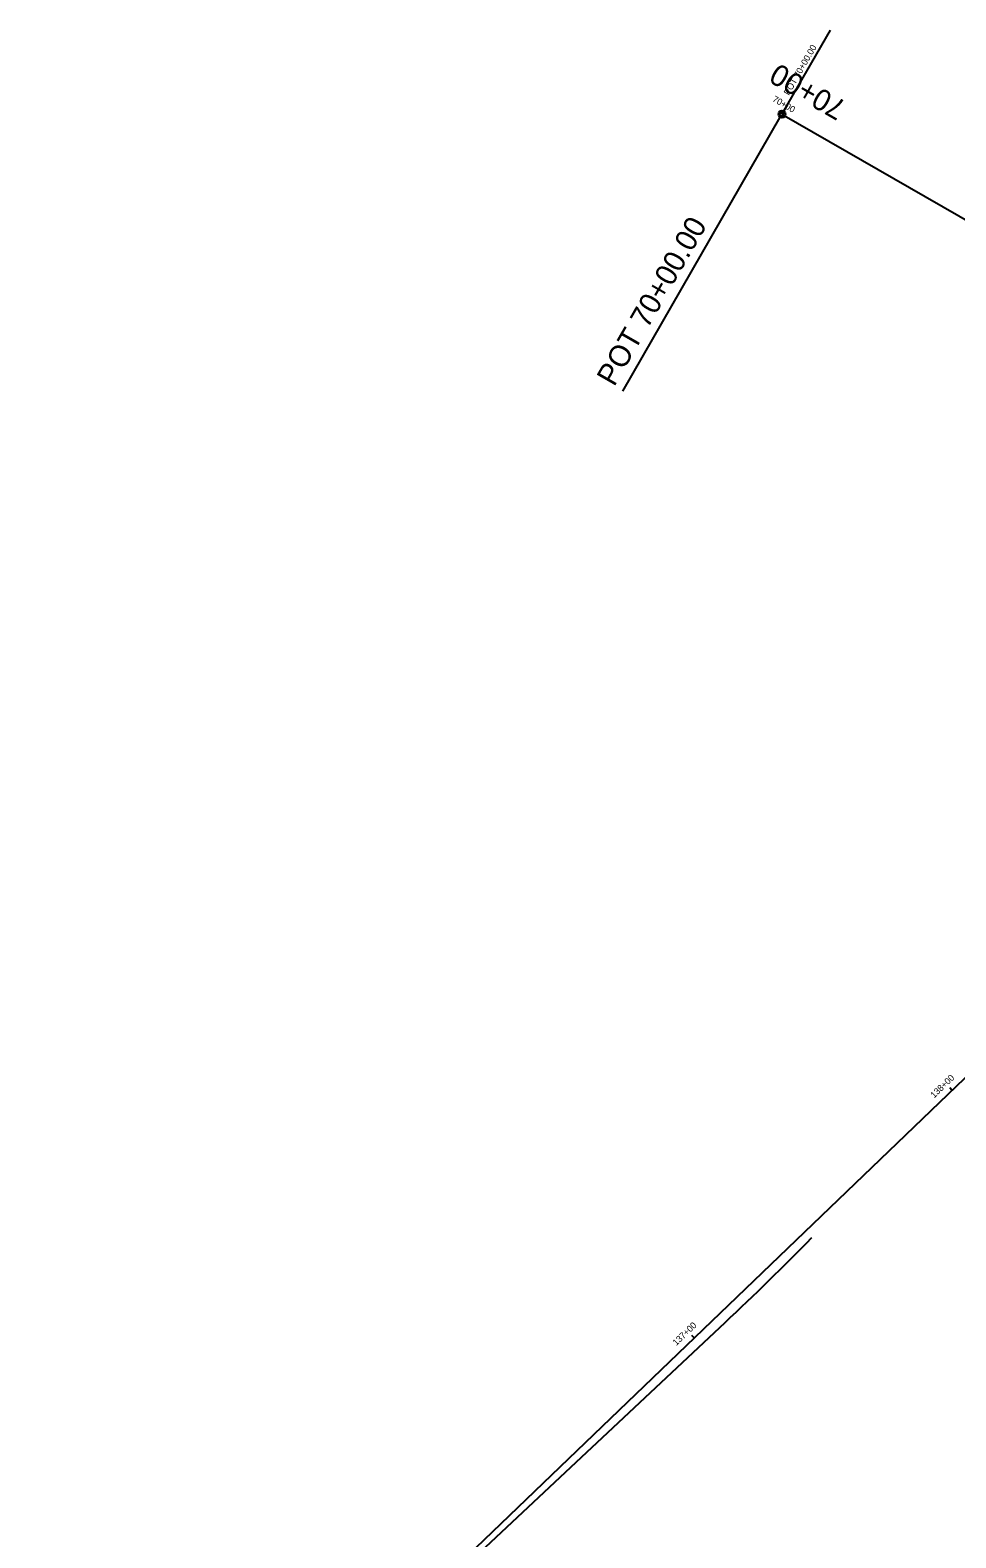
# Model space of a CAD drawing. Extents: x 2252491 to 2257126, y 13788370 to 13792743.
# Drawn here: x 2255062.9 to 2255321.9, y 13791067.5 to 13791489.3 of the extents above; entities that cross this region are included whole.
import ezdxf

# ---------------------------------------------------------------- set-up
doc = ezdxf.new("R2010")
doc.units = 0
for name, color, linetype in [('D_ALIGN_1', 7, 'Continuous'), ('D_ALIGN_ANNO_1', 7, 'Continuous'), ('D_ALIGN_ANNO_DOVE_CROSSING', 7, 'Continuous'), ('D_ALIGN_ANNO_DOVE_CROSSING_30', 7, 'Continuous'), ('D_ALIGN_DOVE_CROSSING', 7, 'Continuous'), ('Default', 7, 'Continuous')]:
    doc.layers.add(name, color=color, linetype=linetype)

msp = doc.modelspace()

# ---------------------------------------------------------------- linework, layer by layer
at = {"layer": 'D_ALIGN_1'}
msp.add_line((2255062.92, 13790944.99), (2255367.32, 13791237.32), dxfattribs=at)
at = {"layer": 'D_ALIGN_ANNO_1'}
for p, q in [((2255320.85, 13791192.69), (2255320.23, 13791193.34)), ((2255248.73, 13791123.43), (2255248.1, 13791124.08))]:
    msp.add_line(p, q, dxfattribs=at)
at = {"layer": 'D_ALIGN_ANNO_DOVE_CROSSING'}
for p, q in [((2255228.71, 13791388.29), (2255272.8, 13791464.93)), ((2255273.29, 13791465.8), (2255274.79, 13791468.4))]:
    msp.add_line(p, q, dxfattribs=at)
msp.add_circle((2255273.29, 13791465.8), 1, dxfattribs=at)
at = {"layer": 'D_ALIGN_ANNO_DOVE_CROSSING_30'}
for p, q in [((2255273.59, 13791466.32), (2255286.82, 13791489.31)), ((2255273.29, 13791465.8), (2255273.74, 13791466.58))]:
    msp.add_line(p, q, dxfattribs=at)
msp.add_circle((2255273.29, 13791465.8), 0.6, dxfattribs=at)
at = {"layer": 'D_ALIGN_DOVE_CROSSING'}
msp.add_line((2255273.29, 13791465.8), (2255371.02, 13791409.58), dxfattribs=at)
at = {"layer": 'Default'}
msp.add_line((2255072.31, 13790954.36), (2255257.38, 13791127.71), dxfattribs=at)
msp.add_arc((2254744.67, 13791675.1), 750, 313.12633, 315.71793, dxfattribs=at)

# ---------------------------------------------------------------- texts
at = {"layer": 'D_ALIGN_ANNO_1'}
for s, p in [('138+00', (2255315.85, 13791190.38)), ('137+00', (2255243.72, 13791121.12))]:
    msp.add_text(s, height=1.8, rotation=43.8407, dxfattribs=at).set_placement(p)
at = {"layer": 'D_ALIGN_ANNO_DOVE_CROSSING'}
for s, rotation, p in [('70+00', 150.091, (2255291.74, 13791469.03)), ('POT 70+00.00', 60.091, (2255226.33, 13791389.35))]:
    msp.add_text(s, height=6, rotation=rotation, dxfattribs=at).set_placement(p)
at = {"layer": 'D_ALIGN_ANNO_DOVE_CROSSING_30'}
for s, rotation, p in [('POT 70+00.00', 60.091, (2255275.21, 13791470.93)), ('70+00', 330.091, (2255270.45, 13791469.51))]:
    msp.add_text(s, height=1.8, rotation=rotation, dxfattribs=at).set_placement(p)

doc.saveas('drawing.dxf')
